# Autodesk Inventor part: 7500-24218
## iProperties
Shininess: 64.0
Length Units: 11269
Angle Units: 11279
Time Units: 11290
Mass Units: 11283
Length Display Precision: 3
Angle Display Precision: 2
Compacted: True
Company: SPI GmbH
Created: 2004-04
Part Number: 7500-24218
Material: Neutral
Document SubType Name: Blech
Designer: klemens
Manufacturer: Standard
Standards Organization: Custom
Description: FLACHSTECKERHÜLSE
Cost Center: 0 kg
Authority: 41 mm^3
Density: 0.0
Volumn: 0.0
Area: 0.0
PropertySet Name: Model Information
Control State: 0
Master: False
Checked Out: False
SPI-MACHINE: Neutral
SPI-MATERIAL: Neutral
SPI-THICKNESS: 0.5
SPI-USE-INCH: False
AIMD_MATERIAL: MS 63 CuZu37
AIMD_DESCRIPTION: STECKERVERBINDUNG
AIMD_PARTNO: Z403-F5022820
SaveDate: 2005-07-07
SaveTime: 17:09
TotalMass: 0 kg
TotalVolume: 41 mm^3
SM_Thickness: 0,5 mm
SM_Style: Neutral
SM_Extents: N/A
SM_Extents_Width: 0.000 mm
SM_Extents_Length: 0.000 mm
Author: klemens
Title: FLACHSTECKERHÜLSE
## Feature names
1. Spiegeln1 [Mirror]
2. Spiegeln3 [Mirror]
3. Platte1
4. Ausklinkung1
5. Ausklinkung2
